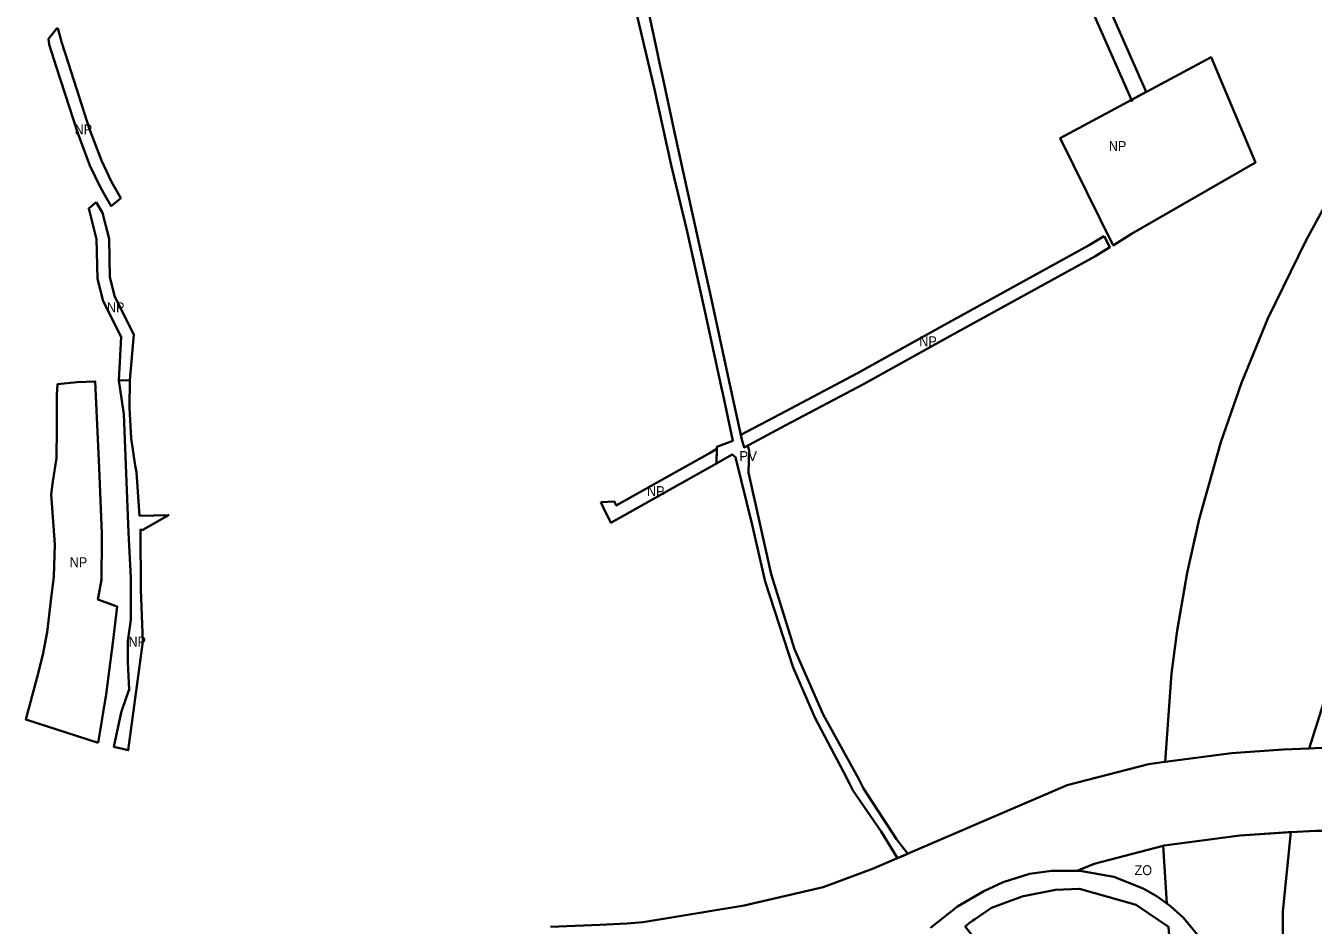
# Model space of a CAD drawing. Extents: x -650276 to -642489, y -1074311 to -1066658.
# Drawn here: x -649415 to -647860, y -1069166 to -1068079 of the extents above; entities that cross this region are included whole.
import ezdxf

# ---------------------------------------------------------------- set-up
doc = ezdxf.new("R2010")
doc.units = 0
doc.header["$LTSCALE"] = 4.8
doc.header["$PDMODE"] = 32
doc.header["$PDSIZE"] = 2.4
for name, color, linetype, lineweight in [('15', 7, 'Continuous', 35), ('24', 7, 'Continuous', 35), ('25', 7, 'Continuous', 35), ('42', 7, 'Continuous', 35), ('48', 7, 'Continuous', 35)]:
    doc.layers.add(name, color=color, linetype=linetype, lineweight=lineweight)
doc.layers.add('62', color=7, linetype='Continuous')
doc.layers.add('63', color=7, linetype='Continuous')

msp = doc.modelspace()

# ---------------------------------------------------------------- linework, layer by layer
at = {"layer": '15'}
for points in [[(-648668.92, -1068032.96), (-648651.89, -1068111.95), (-648649.74, -1068121.95), (-648644.73, -1068145.27), (-648630.99, -1068209.19), (-648610.14, -1068304.32), (-648587.39, -1068405.82), (-648559.91, -1068532.62), (-648549.84, -1068578.65), (-648547.25, -1068588.14), (-648542.93, -1068586.13), (-648541.74, -1068589.27)], [(-648349.419, -1069079.223), (-648362.06, -1069084.664), (-648381.44, -1069052.48), (-648415.29, -1069003.16), (-648419.78, -1068994.25), (-648427.21, -1068980.13), (-648461.22, -1068915.44), (-648488.09, -1068854.16), (-648521.92, -1068750.34), (-648537.29, -1068681.95), (-648557.4, -1068599.9), (-648559.44, -1068598.37), (-648561.49, -1068596.84), (-648580.66, -1068607.64), (-648579.97, -1068587.39), (-648560.79, -1068580.12), (-648572.95, -1068522.97), (-648573.96, -1068518.34), (-648594.38, -1068425.02), (-648615.87, -1068327.3), (-648634.84, -1068248.76), (-648655.88, -1068153.63), (-648662.71, -1068124.76), (-648677.61, -1068061.74)], [(-648541.74, -1068589.27), (-648541.25, -1068592.3), (-648541.89, -1068618.64), (-648514.35, -1068741.53), (-648486.25, -1068831.83), (-648451.76, -1068910.91), (-648409.15, -1068988.44), (-648402.76, -1069000.2), (-648363.11, -1069061.72), (-648349.419, -1069079.223)]]:
    msp.add_lwpolyline(points, dxfattribs=at)
at = {"layer": '24'}
for points in [[(-647864.531, -1068951.823), (-647895.901, -1068953.392), (-647958.168, -1068957.73), (-648038.596, -1068968.281), (-648038.759, -1068968.54)], [(-647808.28, -1068952.066), (-647850.043, -1068951.098), (-647864.531, -1068951.823)], [(-648038.759, -1068968.54), (-648038.746, -1068968.301), (-648058.764, -1068970.927), (-648156.739, -1068996.273), (-648392.002, -1069097.554), (-648451.865, -1069119.456), (-648547.243, -1069141.81), (-648668.959, -1069161.838), (-648688.912, -1069163.603), (-648721.315, -1069164.952), (-648781.015, -1069167.44)], [(-648040.705, -1069069.547), (-648039.666, -1069069.279), (-647948.18, -1069057.276), (-647886.615, -1069053.052), (-647856.541, -1069051.548), (-647848.615, -1069051.679), (-647842.888, -1069051.774), (-647814.401, -1069052.246)], [(-648322.14, -1069168.56), (-648306.83, -1069156.57), (-648289.25, -1069142.79), (-648257.5, -1069124.41), (-648234.22, -1069113.6), (-648202.46, -1069103.3), (-648175.65, -1069099.64), (-648144.866, -1069099.987), (-648124.327, -1069091.181), (-648040.705, -1069069.547)]]:
    msp.add_lwpolyline(points, dxfattribs=at)
at = {"layer": '25'}
msp.add_line((-648038.596, -1068968.281), (-647958.168, -1068957.73), dxfattribs=at)
for points in [[(-647801.797, -1068219.34), (-647843.6, -1068292.629), (-647868.214, -1068337.803), (-647914.339, -1068432.512), (-647946.187, -1068510.254), (-647971.074, -1068581.98), (-647997.27, -1068674.747), (-648011.775, -1068739.718), (-648023.914, -1068809.332), (-648030.73, -1068861.213), (-648038.596, -1068968.281)], [(-647958.168, -1068957.73), (-647895.901, -1068953.392), (-647864.531, -1068951.823), (-647847.197, -1068897.199), (-647847.034, -1068896.687), (-647846.989, -1068896.545)], [(-647948.18, -1069057.276), (-648039.666, -1069069.279), (-648040.705, -1069069.548), (-648036.291, -1069139.458)], [(-647886.615, -1069053.052), (-647889.927, -1069053.218), (-647948.18, -1069057.276)], [(-647893.553, -1069279.017), (-647896.67, -1069213.573), (-647896.362, -1069149.171), (-647886.615, -1069053.052)], [(-648036.291, -1069139.458), (-648031.92, -1069142.67), (-648016.36, -1069156.54), (-647993.8, -1069184.11)]]:
    msp.add_lwpolyline(points, dxfattribs=at)
at = {"layer": '42'}
for points in [[(-648100.37, -1069107.1), (-648065.16, -1069121.12), (-648048.06, -1069130.81), (-648036.291, -1069139.458), (-648040.705, -1069069.547), (-648124.327, -1069091.181), (-648144.867, -1069099.987), (-648139.27, -1069100.05), (-648100.37, -1069107.1)], [(-648015, -1069300), (-648033, -1069189), (-648034.421, -1069167.61), (-648071.9, -1069142.06), (-648073.66, -1069140.86), (-648141.92, -1069121.66), (-648171.14, -1069122.83), (-648207.77, -1069129.95), (-648209.89, -1069130.36), (-648226.51, -1069136.57), (-648248.14, -1069144.65), (-648268.87, -1069158.61), (-648270.92, -1069159.99), (-648275.19, -1069162.87), (-648280.1, -1069166.97), (-648203.01, -1069264.73), (-648127.77, -1069361.38), (-648068.71, -1069436.57), (-647967.53, -1069559.94), (-647958.214, -1069571.3), (-647980.331, -1069465.915), (-648010.092, -1069322.087)]]:
    msp.add_lwpolyline(points, close=True, dxfattribs=at)
at = {"layer": '48'}
for points in [[(-648238.748, -1067756.759), (-648256.499, -1067766.091), (-648079.002, -1068168.139)], [(-648079.002, -1068168.139), (-648061.329, -1068158.649), (-648232.676, -1067770.513)], [(-649302.681, -1068507.363), (-649296.55, -1068548.09), (-649290.93, -1068690.93), (-649287.98, -1068745.74), (-649288.19, -1068786.39), (-649288.24, -1068796.6), (-649291.64, -1068821.88), (-649291.87, -1068848.02), (-649290.28, -1068880.82), (-649293.33, -1068889.65), (-649299.91, -1068908.66), (-649308.65, -1068950), (-649293.04, -1068953.81), (-649291.32, -1068954.23), (-649281.01, -1068876.69), (-649273.66, -1068822.58), (-649275.96, -1068759.73), (-649276.43, -1068688.29), (-649276.474, -1068687.673), (-649272.755, -1068687.618)], [(-649277.655, -1068670.983), (-649281.4, -1068618.05), (-649282.97, -1068610.04), (-649287.71, -1068577.14), (-649289.74, -1068540.2), (-649289.24, -1068506.8), (-649302.681, -1068507.363)], [(-649272.755, -1068687.618), (-649272.69, -1068687.58), (-649242.507, -1068669.925), (-649277.655, -1068670.983)]]:
    msp.add_lwpolyline(points, dxfattribs=at)
for points in [[(-649376.467, -1068081.552), (-649377.77, -1068082.44), (-649387.46, -1068094.51), (-649386.74, -1068101.31), (-649377.81, -1068129), (-649352.11, -1068208.65), (-649339.94, -1068241.13), (-649337.52, -1068247.59), (-649324.66, -1068274.3), (-649319.551, -1068283.382), (-649312.087, -1068296.653), (-649300.305, -1068287.002), (-649311.352, -1068267.362), (-649323.711, -1068241.693), (-649337.178, -1068205.751), (-649337.942, -1068203.713), (-649363.534, -1068124.395), (-649371.987, -1068098.185)], [(-648101.42, -1068344.28), (-648079.33, -1068330.03), (-647929.45, -1068244.16), (-647971.35, -1068144.48), (-647982.969, -1068116.575), (-648165.28, -1068214.465)], [(-649330.038, -1068291.976), (-649339.046, -1068299.359), (-649329.644, -1068336.779), (-649328.386, -1068384.468), (-649321.727, -1068411.472), (-649299.894, -1068454.728), (-649302.681, -1068507.363), (-649289.24, -1068506.8), (-649284.59, -1068451.76), (-649307.57, -1068406.23), (-649313.42, -1068382.51), (-649314.27, -1068336.41), (-649314.693, -1068334.727), (-649322.18, -1068304.93)], [(-648112.198, -1068333.037), (-648112.92, -1068333.424), (-648131.034, -1068344.388), (-648305.242, -1068440.3), (-648410.111, -1068498.408), (-648503.768, -1068547.914), (-648551.041, -1068573.16), (-648549.84, -1068578.65), (-648547.25, -1068588.14), (-648496.73, -1068561.16), (-648402.97, -1068511.6), (-648297.99, -1068453.43), (-648123.53, -1068357.38), (-648105.49, -1068346.46)], [(-649327.679, -1068945.222), (-649318.13, -1068886.42), (-649314.07, -1068855.33), (-649310.01, -1068824.2), (-649304.66, -1068780.33), (-649327.8, -1068771.82), (-649323.68, -1068748.06), (-649323.1, -1068699.28), (-649323.02, -1068692.1), (-649326.53, -1068612.89), (-649331.151, -1068508.557), (-649353.17, -1068509.48), (-649376.77, -1068511.96), (-649377.52, -1068525.1), (-649377.56, -1068564.89), (-649378.08, -1068601.24), (-649382.46, -1068629.34), (-649384.31, -1068644.92), (-649379.97, -1068704.98), (-649381.06, -1068744.69), (-649383.78, -1068766.6), (-649389.34, -1068811.43), (-649394.48, -1068838.89), (-649401.31, -1068865.78), (-649415.09, -1068917.1)], [(-648720.238, -1068654.205), (-648717.32, -1068660.24), (-648708.14, -1068679.23), (-648645.69, -1068644.27), (-648643.654, -1068643.123), (-648580.66, -1068607.64), (-648580.062, -1068590.087), (-648588.022, -1068594.571), (-648653.034, -1068631.191), (-648701.568, -1068658.36), (-648703.816, -1068653.711)]]:
    msp.add_lwpolyline(points, close=True, dxfattribs=at)
msp.add_point((-648079.002, -1068168.139), dxfattribs=at)

# ---------------------------------------------------------------- texts
at = {"layer": '62', "width": 0.95}
for s, p in [('NP', (-649355.985, -1068209.967)), ('NP', (-648106.583, -1068230.041)), ('NP', (-649316.985, -1068424.967)), ('NP', (-648335.583, -1068466.041)), ('NP', (-648664.583, -1068647.041)), ('NP', (-649361.985, -1068732.967)), ('NP', (-649290.985, -1068828.967)), ('ZO', (-648075.473, -1069105.058))]:
    msp.add_text(s, height=12, dxfattribs=at).set_placement(p)
at = {"layer": '63'}
msp.add_text('PV', height=12, dxfattribs=at).set_placement((-648552.984, -1068604.692))

doc.saveas('drawing.dxf')
